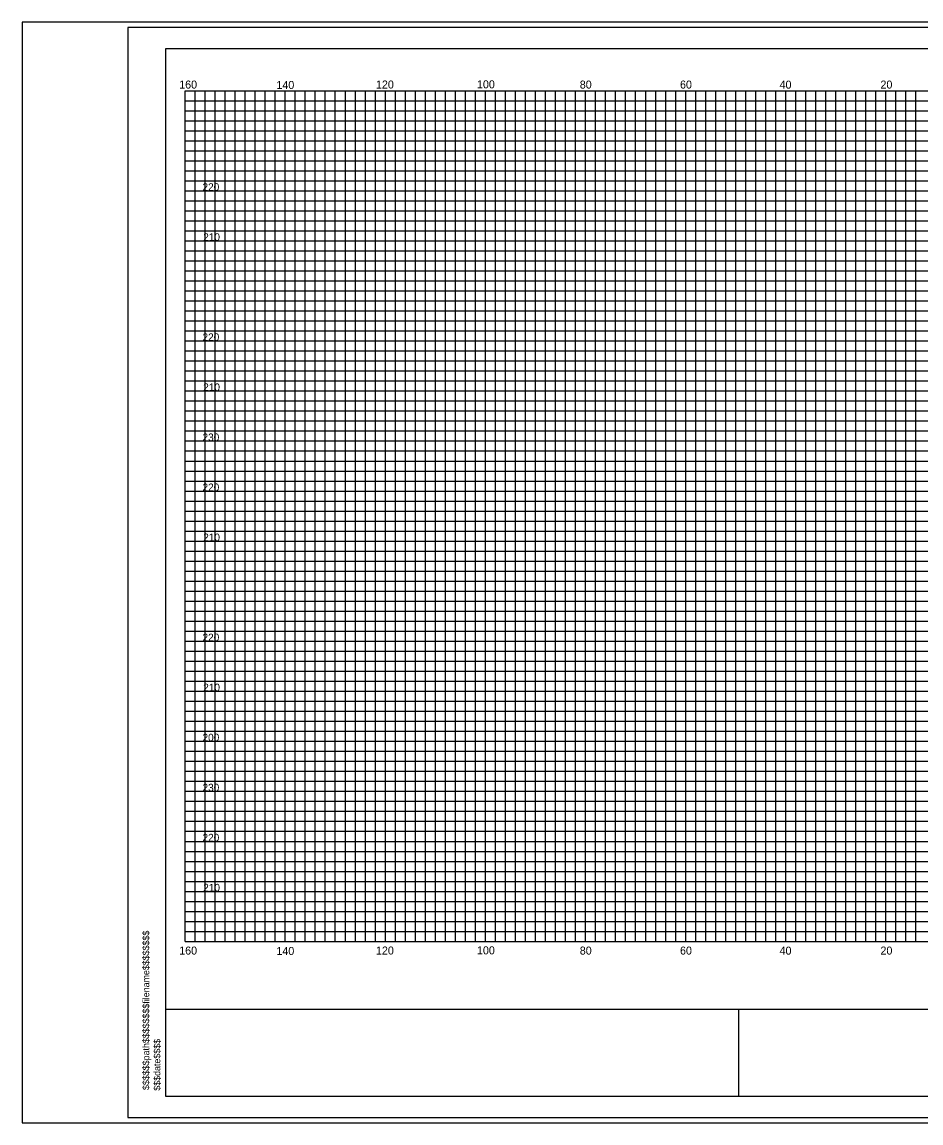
# Model space of a CAD drawing. Extents: x 967 to 1326, y 964 to 2584.
# Drawn here: x 967.4 to 1147, y 1243.7 to 1463.7 of the extents above; entities that cross this region are included whole.
import ezdxf

# ---------------------------------------------------------------- set-up
doc = ezdxf.new("R2010")
doc.units = 0
for name, color, linetype in [('Default', 7, 'Continuous'), ('RD_GPK_XS_Cell', 7, 'Continuous'), ('RD_XS_ExGround', 7, 'Continuous'), ('RD_XS_ExPaveRet', 7, 'Continuous'), ('RD_XS_Misc_Line', 7, 'Continuous'), ('RD_XS_TX_Elev_EX', 7, 'Continuous')]:
    doc.layers.add(name, color=color, linetype=linetype)

msp = doc.modelspace()

# ---------------------------------------------------------------- linework, layer by layer
at = {"layer": 'RD_GPK_XS_Cell'}
for p, q in [((1000, 1450), (1320, 1450)), ((1000, 1280), (1000, 1450)), ((1010, 1280), (1010, 1450)), ((1020, 1280), (1020, 1450)), ((1030, 1280), (1030, 1450)), ((1040, 1280), (1040, 1450)), ((1050, 1280), (1050, 1450)), ((1060, 1280), (1060, 1450)), ((1070, 1280), (1070, 1450)), ((1080, 1280), (1080, 1450)), ((1090, 1280), (1090, 1450)), ((1100, 1280), (1100, 1450)), ((1110, 1280), (1110, 1450)), ((1120, 1280), (1120, 1450)), ((1130, 1280), (1130, 1450)), ((1140, 1280), (1140, 1450)), ((1000, 1440), (1320, 1440)), ((1000, 1430), (1320, 1430)), ((1000, 1420), (1320, 1420)), ((1000, 1410), (1320, 1410)), ((1000, 1400), (1320, 1400)), ((1000, 1390), (1320, 1390)), ((1000, 1380), (1320, 1380)), ((1000, 1370), (1320, 1370)), ((1000, 1360), (1320, 1360)), ((1000, 1350), (1320, 1350)), ((1000, 1340), (1320, 1340)), ((1000, 1330), (1320, 1330)), ((1000, 1320), (1320, 1320)), ((1000, 1310), (1320, 1310)), ((1000, 1300), (1320, 1300)), ((1000, 1290), (1320, 1290)), ((1000, 1280), (1320, 1280))]:
    msp.add_line(p, q, dxfattribs=at)
at = {"layer": 'RD_XS_ExGround'}
for p, q in [((1002, 1280), (1002, 1450)), ((1004, 1280), (1004, 1450)), ((1006, 1280), (1006, 1450)), ((1008, 1280), (1008, 1450)), ((1012, 1280), (1012, 1450)), ((1014, 1280), (1014, 1450)), ((1016, 1280), (1016, 1450)), ((1018, 1280), (1018, 1450)), ((1022, 1280), (1022, 1450)), ((1024, 1280), (1024, 1450)), ((1026, 1280), (1026, 1450)), ((1028, 1280), (1028, 1450)), ((1032, 1280), (1032, 1450)), ((1034, 1280), (1034, 1450)), ((1036, 1280), (1036, 1450)), ((1038, 1280), (1038, 1450)), ((1042, 1280), (1042, 1450)), ((1044, 1280), (1044, 1450)), ((1046, 1280), (1046, 1450)), ((1048, 1280), (1048, 1450)), ((1052, 1280), (1052, 1450)), ((1054, 1280), (1054, 1450)), ((1056, 1280), (1056, 1450)), ((1058, 1280), (1058, 1450)), ((1062, 1280), (1062, 1450)), ((1064, 1280), (1064, 1450)), ((1066, 1280), (1066, 1450)), ((1068, 1280), (1068, 1450)), ((1072, 1280), (1072, 1450)), ((1074, 1280), (1074, 1450)), ((1076, 1280), (1076, 1450)), ((1078, 1280), (1078, 1450)), ((1082, 1280), (1082, 1450)), ((1084, 1280), (1084, 1450)), ((1086, 1280), (1086, 1450)), ((1088, 1280), (1088, 1450)), ((1092, 1280), (1092, 1450)), ((1094, 1280), (1094, 1450)), ((1096, 1280), (1096, 1450)), ((1098, 1280), (1098, 1450)), ((1102, 1280), (1102, 1450)), ((1104, 1280), (1104, 1450)), ((1106, 1280), (1106, 1450)), ((1108, 1280), (1108, 1450)), ((1112, 1280), (1112, 1450)), ((1114, 1280), (1114, 1450)), ((1116, 1280), (1116, 1450)), ((1118, 1280), (1118, 1450)), ((1122, 1280), (1122, 1450)), ((1124, 1280), (1124, 1450)), ((1126, 1280), (1126, 1450)), ((1128, 1280), (1128, 1450)), ((1132, 1280), (1132, 1450)), ((1134, 1280), (1134, 1450)), ((1136, 1280), (1136, 1450)), ((1138, 1280), (1138, 1450)), ((1142, 1280), (1142, 1450)), ((1144, 1280), (1144, 1450)), ((1146, 1280), (1146, 1450)), ((1000, 1448), (1320, 1448)), ((1000, 1446), (1320, 1446)), ((1000, 1444), (1320, 1444)), ((1000, 1442), (1320, 1442)), ((1000, 1438), (1320, 1438)), ((1000, 1436), (1320, 1436)), ((1000, 1434), (1320, 1434)), ((1000, 1432), (1320, 1432)), ((1000, 1428), (1320, 1428)), ((1000, 1426), (1320, 1426)), ((1000, 1424), (1320, 1424)), ((1000, 1422), (1320, 1422)), ((1000, 1418), (1320, 1418)), ((1000, 1416), (1320, 1416)), ((1000, 1414), (1320, 1414)), ((1000, 1412), (1320, 1412)), ((1000, 1408), (1320, 1408)), ((1000, 1406), (1320, 1406)), ((1000, 1404), (1320, 1404)), ((1000, 1402), (1320, 1402)), ((1000, 1398), (1320, 1398)), ((1000, 1396), (1320, 1396)), ((1000, 1394), (1320, 1394)), ((1000, 1392), (1320, 1392)), ((1000, 1388), (1320, 1388)), ((1000, 1386), (1320, 1386)), ((1000, 1384), (1320, 1384)), ((1000, 1382), (1320, 1382)), ((1000, 1378), (1320, 1378)), ((1000, 1376), (1320, 1376)), ((1000, 1374), (1320, 1374)), ((1000, 1372), (1320, 1372)), ((1000, 1368), (1320, 1368)), ((1000, 1366), (1320, 1366)), ((1000, 1364), (1320, 1364)), ((1000, 1362), (1320, 1362)), ((1000, 1358), (1320, 1358)), ((1000, 1356), (1320, 1356)), ((1000, 1354), (1320, 1354)), ((1000, 1352), (1320, 1352)), ((1000, 1348), (1320, 1348)), ((1000, 1346), (1320, 1346)), ((1000, 1344), (1320, 1344)), ((1000, 1342), (1320, 1342)), ((1000, 1338), (1320, 1338)), ((1000, 1336), (1320, 1336)), ((1000, 1334), (1320, 1334)), ((1000, 1332), (1320, 1332)), ((1000, 1328), (1320, 1328)), ((1000, 1326), (1320, 1326)), ((1000, 1324), (1320, 1324)), ((1000, 1322), (1320, 1322)), ((1000, 1318), (1320, 1318)), ((1000, 1316), (1320, 1316)), ((1000, 1314), (1320, 1314)), ((1000, 1312), (1320, 1312)), ((1000, 1308), (1320, 1308)), ((1000, 1306), (1320, 1306)), ((1000, 1304), (1320, 1304)), ((1000, 1302), (1320, 1302)), ((1000, 1298), (1320, 1298)), ((1000, 1296), (1320, 1296)), ((1000, 1294), (1320, 1294)), ((1000, 1292), (1320, 1292)), ((1000, 1288), (1320, 1288)), ((1000, 1286), (1320, 1286)), ((1000, 1284), (1320, 1284)), ((1000, 1282), (1320, 1282))]:
    msp.add_line(p, q, dxfattribs=at)
at = {"layer": 'RD_XS_ExPaveRet'}
for points in [[(967.41, 1243.72), (1326.28, 1243.72), (1326.28, 1463.72), (967.41, 1463.72)], [(988.52, 1244.84), (1326.28, 1244.84), (1326.28, 1462.6), (988.52, 1462.6)]]:
    msp.add_lwpolyline(points, close=True, dxfattribs=at)
at = {"layer": 'RD_XS_TX_Elev_EX'}
for p, q in [((996.11, 1248.98), (996.11, 1458.46)), ((996.11, 1458.46), (1323.89, 1458.46)), ((996.11, 1266.49), (1323.89, 1266.49)), ((1110.59, 1248.98), (1110.59, 1266.56)), ((1323.89, 1248.98), (996.11, 1248.98))]:
    msp.add_line(p, q, dxfattribs=at)

# ---------------------------------------------------------------- texts
at = {"layer": 'Default'}
for s, p in [('220', (1003.47, 1430)), ('210', (1003.61, 1420)), ('220', (1003.47, 1400)), ('210', (1003.61, 1390)), ('230', (1003.47, 1380)), ('220', (1003.47, 1370)), ('210', (1003.61, 1360)), ('220', (1003.47, 1340)), ('210', (1003.61, 1330)), ('200', (1003.47, 1320)), ('230', (1003.47, 1310)), ('220', (1003.47, 1300)), ('210', (1003.61, 1290))]:
    msp.add_text(s, height=1.5, dxfattribs=at).set_placement(p)
for s, p in [('$$$$$$path$$$$$$$$filename$$$$$$$$', (992.83, 1250.31)), ('$$$date$$$$', (995.04, 1250.17))]:
    msp.add_text(s, height=1.3258, rotation=90, dxfattribs=at).set_placement(p)
at = {"layer": 'RD_XS_Misc_Line'}
for s, p in [('160', (998.81, 1450.42)), ('120', (1038.12, 1450.43)), ('100', (1058.3, 1450.47)), ('80', (1078.84, 1450.42)), ('60', (1098.86, 1450.42)), ('40', (1118.75, 1450.41)), ('20', (1138.91, 1450.42)), ('140', (1018.23, 1450.34)), ('160', (998.81, 1277.37)), ('140', (1018.23, 1277.29)), ('120', (1038.12, 1277.38)), ('100', (1058.3, 1277.42)), ('80', (1078.84, 1277.37)), ('60', (1098.86, 1277.37)), ('40', (1118.75, 1277.36)), ('20', (1138.91, 1277.37))]:
    msp.add_text(s, height=1.6, dxfattribs=at).set_placement(p)

doc.saveas('drawing.dxf')
